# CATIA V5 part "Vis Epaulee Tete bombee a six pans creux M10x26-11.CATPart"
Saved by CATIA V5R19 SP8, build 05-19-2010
Part number: Vis Epaulée Tetebombee a six pan creux M10x26-11
Nomenclature: 19
Source: Unknown
Description: PART-screw_gb_t_70_2_m10x25-DESC
Bounding box of the stored display mesh (mm): x -5.5 to 26, y -8.743 to 8.75, z -8.75 to 8.75
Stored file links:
  C:\Users\rphgr\Desktop\0_Tapis_TC520B_vitesse\Vis Epaulee Tete bombee a six pans creux M10x26-11.CATPart
  C:\Program Files\Dassault Systemes\B19\win_b64\reffiles\standard\MetricThickPitch.txt
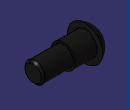
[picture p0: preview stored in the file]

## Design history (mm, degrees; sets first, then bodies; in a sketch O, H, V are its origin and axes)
AxisSystem1: origin (0, 0, 0), X (1, 0, 0), Y (0, 1, 0), Z (0, 0, 1)
Body1 "screw_gb_t_70_2_m10x25" (main body)
  Solid1: solid without history
  Thickness1: Thickness 0.5, Face (face of Solid1; face of Solid1; face of Solid1; face of Solid1; face of Solid1; face of Solid1)
  Sketch1 on ZX plane of AxisSystem1, origin (0, 0, 0), H (0, 0, 1), V (1, 0, 0)
    arc A1 centre (0, 3.1669) radius 9.3055 from (8.75, 0) to (3.3876, -5.5) cw
    point P1 (0, 3.1669)
    point P2 (8.75, 0)
    point P3 (3.3876, -5.5)
    reference projected line E1 through (0, 0) direction (0, 1) from axis of face of Solid1
    reference intersected line E2 through (0, -5.5) direction (1, 0) from face of Solid1
    reference intersected line E3 (2.8876, -5.5) -> (2.8876, -2.0477) from face of Solid1
    reference projected line E4 through (0, 0) direction (0, 1) from axis of face of Solid1
    distance P3 E3 = 0.5
    distance P2 E4 = 8.75
    coincidence: P2 H, P1 E1, P3 E2
  Groove1: profile Sketch1, axis axis of face of Solid1, angle 360
  Split1: SplitPlane face of Solid1
  Sketch2 on ZX plane of AxisSystem1, origin (0, 0, 0), H (0, 0, 1), V (1, 0, 0)
    point P1 (-6, 0)
    line L1 (-6, 0) -> (-6, 11)
    line L2 (-6, 11) -> (-5, 11)
    line L3 (-5, 11) -> (-5, 26)
    line L4 (-5, 26) -> (0, 26)
    point P5 (0, 26)
    axis line L5 (0, -7.7284) -> (0, 34.7223)
    point P6 (0, -7.7284)
    reference intersected line E1 (-8.75, 0) -> (8.75, 0) from face of Split1
    reference intersected line E2 (-8.75, 0) -> (8.75, 0) from face of Split1
    distance L5 L1 = 6
    distance L3 L5 = 5
    distance L2 E1 = 11
    distance L4 E2 = 26
    coincidence: P1 H, P5 V, P6 V
    vertical: L1 V, L3 V, L5 V
    horizontal: L2 H, L4 H
  Shaft1: profile Sketch2, axis Sketch2.L5, angle 360
  Thread1: "M10", diameter 10, depth 15, pitch 1.5, on face of Shaft1 from Sketch2.L3, from face of Shaft1 from Sketch2.L4
  Chamfer1: length 1, angle 45, on edge [face of Shaft1 from Sketch2.L3 | face of Shaft1 from Sketch2.L4]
